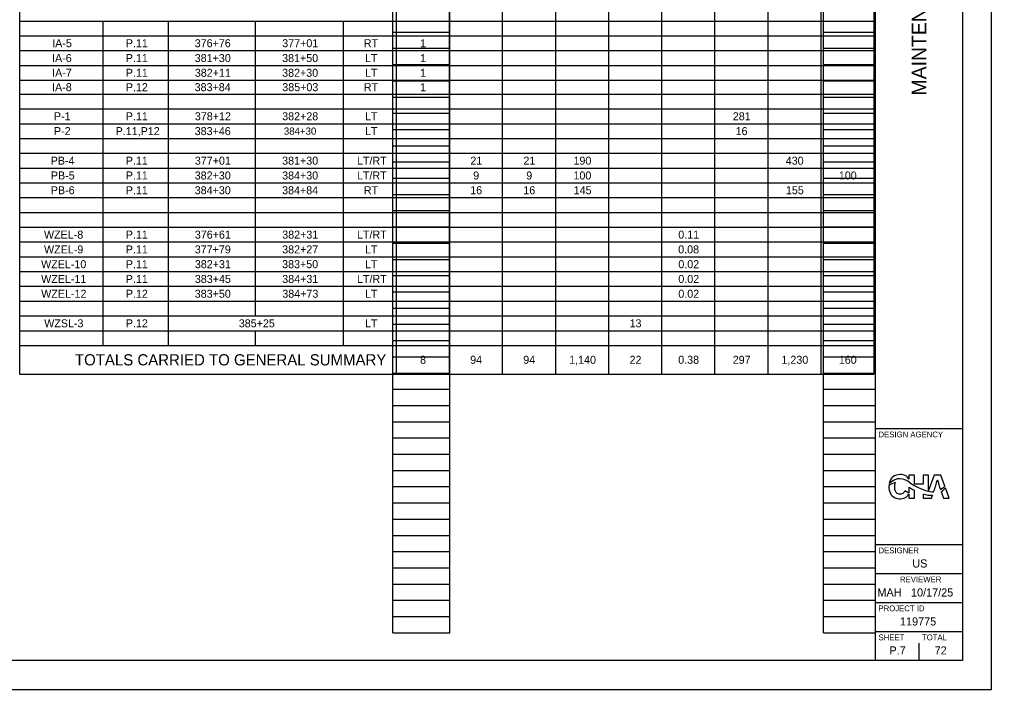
# Model space of a CAD drawing. Extents: x -18.6 to 34, y -8.1 to 37.1.
# Drawn here: x 17.24 to 34, y 0 to 11.56 of the extents above; entities that cross this region are included whole.
import ezdxf

# ---------------------------------------------------------------- set-up
doc = ezdxf.new("R2010")
doc.units = 0
for name, color, linetype in [('SH_Border', 7, 'Continuous'), ('SH_Cut_Line', 7, 'Continuous'), ('SH_Data', 7, 'Continuous'), ('SH_Text', 7, 'Continuous')]:
    doc.layers.add(name, color=color, linetype=linetype)

msp = doc.modelspace()

# ---------------------------------------------------------------- linework, layer by layer
at = {"layer": 'SH_Border'}
for p, q in [((32, 0.5), (32, 21.5)), ((32, 4.5), (33.5, 4.5)), ((32, 2.5), (33.5, 2.5)), ((32, 2), (33.5, 2)), ((32, 1.5), (33.5, 1.5)), ((32, 1), (33.5, 1))]:
    msp.add_line(p, q, dxfattribs=at)
msp.add_lwpolyline([(1.5, 21.5), (33.5, 21.5), (33.5, 0.5), (1.5, 0.5)], close=True, dxfattribs=at)
at = {"layer": 'SH_Cut_Line'}
msp.add_lwpolyline([(0, 0), (34, 0), (34, 22), (0, 22)], close=True, dxfattribs=at)
at = {"layer": 'SH_Data'}
for p, q in [((23.68, 0.98), (23.68, 21.14)), ((24.66, 0.98), (24.66, 21.14)), ((31.1, 0.98), (31.1, 21.14)), ((32, 0.98), (32, 21.14)), ((23.68, 11.34), (24.66, 11.34)), ((31.1, 11.34), (32, 11.34)), ((23.68, 11.06), (24.66, 11.06)), ((31.1, 11.06), (32, 11.06)), ((23.68, 10.78), (24.66, 10.78)), ((31.1, 10.78), (32, 10.78)), ((23.68, 10.5), (24.66, 10.5)), ((31.1, 10.5), (32, 10.5)), ((23.68, 10.22), (24.66, 10.22)), ((31.1, 10.22), (32, 10.22)), ((23.68, 9.94), (24.66, 9.94)), ((31.1, 9.94), (32, 9.94)), ((23.68, 9.66), (24.66, 9.66)), ((31.1, 9.66), (32, 9.66)), ((23.68, 9.38), (24.66, 9.38)), ((31.1, 9.38), (32, 9.38)), ((23.68, 9.1), (24.66, 9.1)), ((31.1, 9.1), (32, 9.1)), ((23.68, 8.82), (24.66, 8.82)), ((31.1, 8.82), (32, 8.82)), ((23.68, 8.54), (24.66, 8.54)), ((31.1, 8.54), (32, 8.54)), ((23.68, 8.26), (24.66, 8.26)), ((31.1, 8.26), (32, 8.26)), ((23.68, 7.98), (24.66, 7.98)), ((31.1, 7.98), (32, 7.98)), ((23.68, 7.7), (24.66, 7.7)), ((31.1, 7.7), (32, 7.7)), ((23.68, 7.42), (24.66, 7.42)), ((31.1, 7.42), (32, 7.42)), ((23.68, 7.14), (24.66, 7.14)), ((31.1, 7.14), (32, 7.14)), ((23.68, 6.86), (24.66, 6.86)), ((31.1, 6.86), (32, 6.86)), ((23.68, 6.58), (24.66, 6.58)), ((31.1, 6.58), (32, 6.58)), ((23.68, 6.3), (24.66, 6.3)), ((31.1, 6.3), (32, 6.3)), ((23.68, 6.02), (24.66, 6.02)), ((31.1, 6.02), (32, 6.02)), ((23.68, 5.74), (24.66, 5.74)), ((31.1, 5.74), (32, 5.74)), ((23.68, 5.46), (24.66, 5.46)), ((31.1, 5.46), (32, 5.46)), ((23.68, 5.18), (24.66, 5.18)), ((31.1, 5.18), (32, 5.18)), ((23.68, 4.9), (24.66, 4.9)), ((31.1, 4.9), (32, 4.9)), ((23.68, 4.62), (24.66, 4.62)), ((31.1, 4.62), (32, 4.62)), ((23.68, 4.34), (24.66, 4.34)), ((31.1, 4.34), (32, 4.34)), ((23.68, 4.06), (24.66, 4.06)), ((31.1, 4.06), (32, 4.06)), ((23.68, 3.78), (24.66, 3.78)), ((31.1, 3.78), (32, 3.78)), ((23.68, 3.5), (24.66, 3.5)), ((31.1, 3.5), (32, 3.5)), ((32.75, 3.5), (32.75, 3.5)), ((23.68, 3.22), (24.66, 3.22)), ((31.1, 3.22), (32, 3.22)), ((23.68, 2.94), (24.66, 2.94)), ((31.1, 2.94), (32, 2.94)), ((23.68, 2.66), (24.66, 2.66)), ((31.1, 2.66), (32, 2.66)), ((23.68, 2.38), (24.66, 2.38)), ((31.1, 2.38), (32, 2.38)), ((23.68, 2.1), (24.66, 2.1)), ((31.1, 2.1), (32, 2.1)), ((23.68, 1.82), (24.66, 1.82)), ((31.1, 1.82), (32, 1.82)), ((23.68, 1.54), (24.66, 1.54)), ((31.1, 1.54), (32, 1.54)), ((23.68, 1.26), (24.66, 1.26)), ((31.1, 1.26), (32, 1.26)), ((23.68, 0.98), (24.66, 0.98)), ((31.1, 0.98), (32, 0.98)), ((32.375, 0.675), (32.375, 0.675)), ((32.75, 0.5), (32.75, 0.8))]:
    msp.add_line(p, q, dxfattribs=at)
at = {"layer": 'SH_Text'}
for p, q in [((17.24, 20.86), (17.24, 5.44)), ((23.735, 20.86), (23.735, 5.44)), ((24.65, 20.86), (24.65, 5.44)), ((25.565, 20.86), (25.565, 5.44)), ((26.48, 20.86), (26.48, 5.44)), ((27.395, 20.86), (27.395, 5.44)), ((28.31, 20.86), (28.31, 5.44)), ((29.225, 20.86), (29.225, 5.44)), ((30.14, 20.86), (30.14, 5.44)), ((31.055, 20.86), (31.055, 5.44)), ((31.97, 20.86), (31.97, 5.44)), ((17.24, 11.53), (23.735, 11.53)), ((18.68, 11.53), (18.68, 5.935)), ((19.805, 11.53), (19.805, 5.935)), ((21.305, 11.53), (21.305, 6.445)), ((22.82, 11.53), (22.82, 5.935)), ((23.735, 11.53), (31.97, 11.53)), ((17.24, 11.275), (31.97, 11.275)), ((17.24, 11.02), (31.97, 11.02)), ((17.24, 10.765), (31.97, 10.765)), ((17.24, 10.51), (31.97, 10.51)), ((17.24, 10.27), (31.97, 10.27)), ((17.24, 10.015), (31.97, 10.015)), ((17.24, 9.76), (31.97, 9.76)), ((17.24, 9.505), (31.97, 9.505)), ((17.24, 9.25), (31.97, 9.25)), ((17.24, 8.995), (31.97, 8.995)), ((17.24, 8.74), (31.97, 8.74)), ((17.24, 8.485), (31.97, 8.485)), ((17.24, 8.23), (31.97, 8.23)), ((17.24, 7.975), (31.97, 7.975)), ((17.24, 7.72), (31.97, 7.72)), ((17.24, 7.465), (31.97, 7.465)), ((17.24, 7.21), (31.97, 7.21)), ((17.24, 6.955), (31.97, 6.955)), ((17.24, 6.7), (31.97, 6.7)), ((17.24, 6.445), (31.97, 6.445)), ((17.24, 6.19), (31.97, 6.19)), ((21.305, 6.19), (21.305, 5.935)), ((17.24, 5.935), (31.97, 5.935)), ((17.24, 5.44), (31.97, 5.44)), ((33.066, 3.619), (33.069, 3.619))]:
    msp.add_line(p, q, dxfattribs=at)
for points in [[(33.196, 3.508), (33.126, 3.7), (33.012, 3.7), (32.915, 3.431), (32.915, 3.7), (32.822, 3.7), (32.822, 3.543), (32.669, 3.543), (32.669, 3.7), (32.576, 3.7), (32.576, 3.629)], [(32.576, 3.492), (32.576, 3.389), (32.507, 3.43)], [(32.576, 3.37), (32.576, 3.3), (32.669, 3.3), (32.669, 3.439)], [(32.822, 3.373), (32.822, 3.3), (32.867, 3.3), (32.915, 3.3), (32.964, 3.3), (32.981, 3.351)], [(33.133, 3.413), (33.144, 3.383), (33.173, 3.3), (33.272, 3.3), (33.206, 3.481)]]:
    msp.add_lwpolyline(points, dxfattribs=at)
for centre, radius, start, end in [((32.418, 3.503), 0.205, 88.0817, 126.0325), ((32.43, 3.514), 0.194, 64.9016, 91.2438), ((32.442, 3.551), 0.155, 30.3756, 63.3712), ((32.471, 3.495), 0.242, 173.6843, 214.2778), ((32.441, 3.209), 0.376, 105.7483, 123.9538), ((32.414, 3.529), 0.181, 129.6629, 172.5664), ((32.505, 3.249), 0.407, 114.8364, 131.7457), ((32.516, 3.499), 0.192, 157.8882, 204.8663), ((32.417, 3.436), 0.201, 63.1724, 114.4396), ((32.183, 2.916), 0.771, 57.2913, 65.1), ((33.592, 5.1), 1.829, 237.1308, 240.4227), ((31.298, 4.056), 1.821, 339.3263, 346.125), ((34.073, 3.831), 1.026, 191.9132, 201.6837), ((32.347, 3.41), 0.0923, 214.2778, 222.6269), ((32.404, 3.447), 0.0681, 204.8663, 223.055), ((32.418, 3.46), 0.0871, 223.055, 273.5972), ((32.424, 3.461), 0.0879, 269.2163, 339.4439), ((32.441, 3.453), 0.159, 294.1165, 328.289), ((33.232, 4.512), 1.213, 237.2686, 242.3197), ((33.204, 4.445), 1.067, 241.1998, 252.5446), ((32.953, 3.737), 0.386, 250.2087, 274.1935), ((32.979, 3.72), 0.308, 251.9229, 274.261), ((32.877, 3.865), 0.479, 300.42, 311.7894), ((32.822, 3.823), 0.515, 307.219, 318.2934), ((32.407, 3.465), 0.174, 222.6269, 271.9347), ((32.423, 3.511), 0.219, 267.5421, 292.3552)]:
    msp.add_arc(centre, radius, start, end, dxfattribs=at)

# ---------------------------------------------------------------- texts
at = {"layer": 'SH_Data'}
msp.add_text('MAINTENANCE OF TRAFFIC NOTES', height=0.25, rotation=90, dxfattribs=at).set_placement((32.875, 10.247))
for s, height, p in [('DESIGN AGENCY', 0.1, (32.05, 4.35)), ('DESIGNER', 0.1, (32.05, 2.35)), ('US', 0.14, (32.633, 2.105)), ('REVIEWER', 0.1, (32.422, 1.85)), ('MAH', 0.14, (32.032, 1.605)), ('10/17/25', 0.14, (32.611, 1.605)), ('PROJECT ID', 0.1, (32.05, 1.35)), ('119775', 0.14, (32.421, 1.105)), ('SHEET', 0.1, (32.05, 0.85)), ('TOTAL', 0.1, (32.8, 0.85)), ('P.7', 0.14, (32.239, 0.605)), ('72', 0.14, (33.019, 0.605))]:
    msp.add_text(s, height=height, dxfattribs=at).set_placement(p)
at = {"layer": 'SH_Text'}
for s, height, p in [('IA-5', 0.138, (17.805, 11.079)), ('P.11', 0.138, (19.073, 11.079)), ('376+76', 0.138, (20.262, 11.079)), ('377+01', 0.138, (21.771, 11.079)), ('RT', 0.138, (23.178, 11.079)), ('1', 0.138, (24.148, 11.079)), ('IA-6', 0.138, (17.803, 10.823)), ('P.11', 0.138, (19.073, 10.823)), ('381+30', 0.138, (20.262, 10.823)), ('381+50', 0.138, (21.769, 10.823)), ('LT', 0.138, (23.197, 10.823)), ('1', 0.138, (24.148, 10.823)), ('IA-7', 0.138, (17.804, 10.569)), ('P.11', 0.138, (19.073, 10.569)), ('382+11', 0.138, (20.264, 10.569)), ('382+30', 0.138, (21.769, 10.569)), ('LT', 0.138, (23.197, 10.569)), ('1', 0.138, (24.148, 10.569)), ('IA-8', 0.138, (17.803, 10.321)), ('P.12', 0.138, (19.074, 10.321)), ('383+84', 0.138, (20.261, 10.321)), ('385+03', 0.138, (21.772, 10.321)), ('RT', 0.138, (23.178, 10.321)), ('1', 0.138, (24.148, 10.321)), ('P-1', 0.138, (17.835, 9.819)), ('P.11', 0.138, (19.073, 9.819)), ('378+12', 0.138, (20.264, 9.819)), ('382+28', 0.138, (21.77, 9.819)), ('LT', 0.138, (23.197, 9.819)), ('281', 0.138, (29.539, 9.819)), ('P-2', 0.138, (17.835, 9.563)), ('P.11,P12', 0.138, (18.899, 9.563)), ('383+46', 0.138, (20.262, 9.563)), ('384+30', 0.1242, (21.799, 9.57)), ('LT', 0.138, (23.197, 9.563)), ('16', 0.138, (29.587, 9.563)), ('PB-4', 0.138, (17.779, 9.053)), ('P.11', 0.138, (19.073, 9.053)), ('377+01', 0.138, (20.264, 9.053)), ('381+30', 0.138, (21.769, 9.053)), ('LT/RT', 0.138, (23.059, 9.053)), ('21', 0.138, (25.014, 9.053)), ('21', 0.138, (25.929, 9.053)), ('190', 0.138, (26.792, 9.053)), ('430', 0.138, (30.452, 9.053)), ('PB-5', 0.138, (17.782, 8.798)), ('P.11', 0.138, (19.073, 8.798)), ('382+30', 0.138, (20.262, 8.798)), ('384+30', 0.138, (21.769, 8.798)), ('LT/RT', 0.138, (23.059, 8.798)), ('9', 0.138, (25.063, 8.798)), ('9', 0.138, (25.978, 8.798)), ('100', 0.138, (26.792, 8.798)), ('100', 0.138, (31.367, 8.798)), ('PB-6', 0.138, (17.781, 8.543)), ('P.11', 0.138, (19.073, 8.543)), ('384+30', 0.138, (20.262, 8.543)), ('384+84', 0.138, (21.769, 8.543)), ('RT', 0.138, (23.178, 8.543)), ('16', 0.138, (25.012, 8.543)), ('16', 0.138, (25.927, 8.543)), ('145', 0.138, (26.795, 8.543)), ('155', 0.138, (30.455, 8.543)), ('WZEL-8', 0.138, (17.663, 7.778)), ('P.11', 0.138, (19.073, 7.778)), ('376+61', 0.138, (20.264, 7.778)), ('382+31', 0.138, (21.771, 7.778)), ('LT/RT', 0.138, (23.059, 7.778)), ('0.11', 0.138, (28.599, 7.778)), ('WZEL-9', 0.138, (17.664, 7.523)), ('P.11', 0.138, (19.073, 7.523)), ('377+79', 0.138, (20.263, 7.523)), ('382+27', 0.138, (21.77, 7.523)), ('LT', 0.138, (23.197, 7.523)), ('0.08', 0.138, (28.598, 7.523)), ('WZEL-10', 0.138, (17.613, 7.268)), ('P.11', 0.138, (19.073, 7.268)), ('382+31', 0.138, (20.264, 7.268)), ('383+50', 0.138, (21.769, 7.268)), ('LT', 0.138, (23.197, 7.268)), ('0.02', 0.138, (28.6, 7.268)), ('WZEL-11', 0.138, (17.614, 7.013)), ('P.11', 0.138, (19.073, 7.013)), ('383+45', 0.138, (20.264, 7.013)), ('384+31', 0.138, (21.771, 7.013)), ('LT/RT', 0.138, (23.059, 7.013)), ('0.02', 0.138, (28.6, 7.013)), ('WZEL-12', 0.138, (17.615, 6.758)), ('P.12', 0.138, (19.074, 6.758)), ('383+50', 0.138, (20.262, 6.758)), ('384+73', 0.138, (21.772, 6.758)), ('LT', 0.138, (23.197, 6.758)), ('0.02', 0.138, (28.6, 6.758)), ('WZSL-3', 0.138, (17.667, 6.248)), ('P.12', 0.138, (19.074, 6.248)), ('385+25', 0.138, (21.022, 6.248)), ('LT', 0.138, (23.197, 6.248)), ('13', 0.138, (27.759, 6.248)), ('TOTALS CARRIED TO GENERAL SUMMARY', 0.1932, (18.197, 5.591)), ('8', 0.138, (24.147, 5.619)), ('94', 0.138, (25.011, 5.619)), ('94', 0.138, (25.926, 5.619)), ('1,140', 0.138, (26.718, 5.619)), ('22', 0.138, (27.759, 5.619)), ('0.38', 0.138, (28.598, 5.619)), ('297', 0.138, (29.538, 5.619)), ('1,230', 0.138, (30.378, 5.619)), ('160', 0.138, (31.367, 5.619))]:
    msp.add_text(s, height=height, dxfattribs=at).set_placement(p)

doc.saveas('drawing.dxf')
